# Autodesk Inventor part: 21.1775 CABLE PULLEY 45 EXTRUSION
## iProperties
Company: MiniTec Framing Systems, LLC
Created: 2007-05
Part Number: 21.1775 CABLE PULLEY 45 EXTRUSION
Material: Aluminum-6061
Document SubType Name: Modeling
Designer: Andy Moles
Density: 2.71 g/cm^3
Author: Andy Moles
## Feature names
1. Extrusion1
2. Extrusion2
3. Extrusion3
